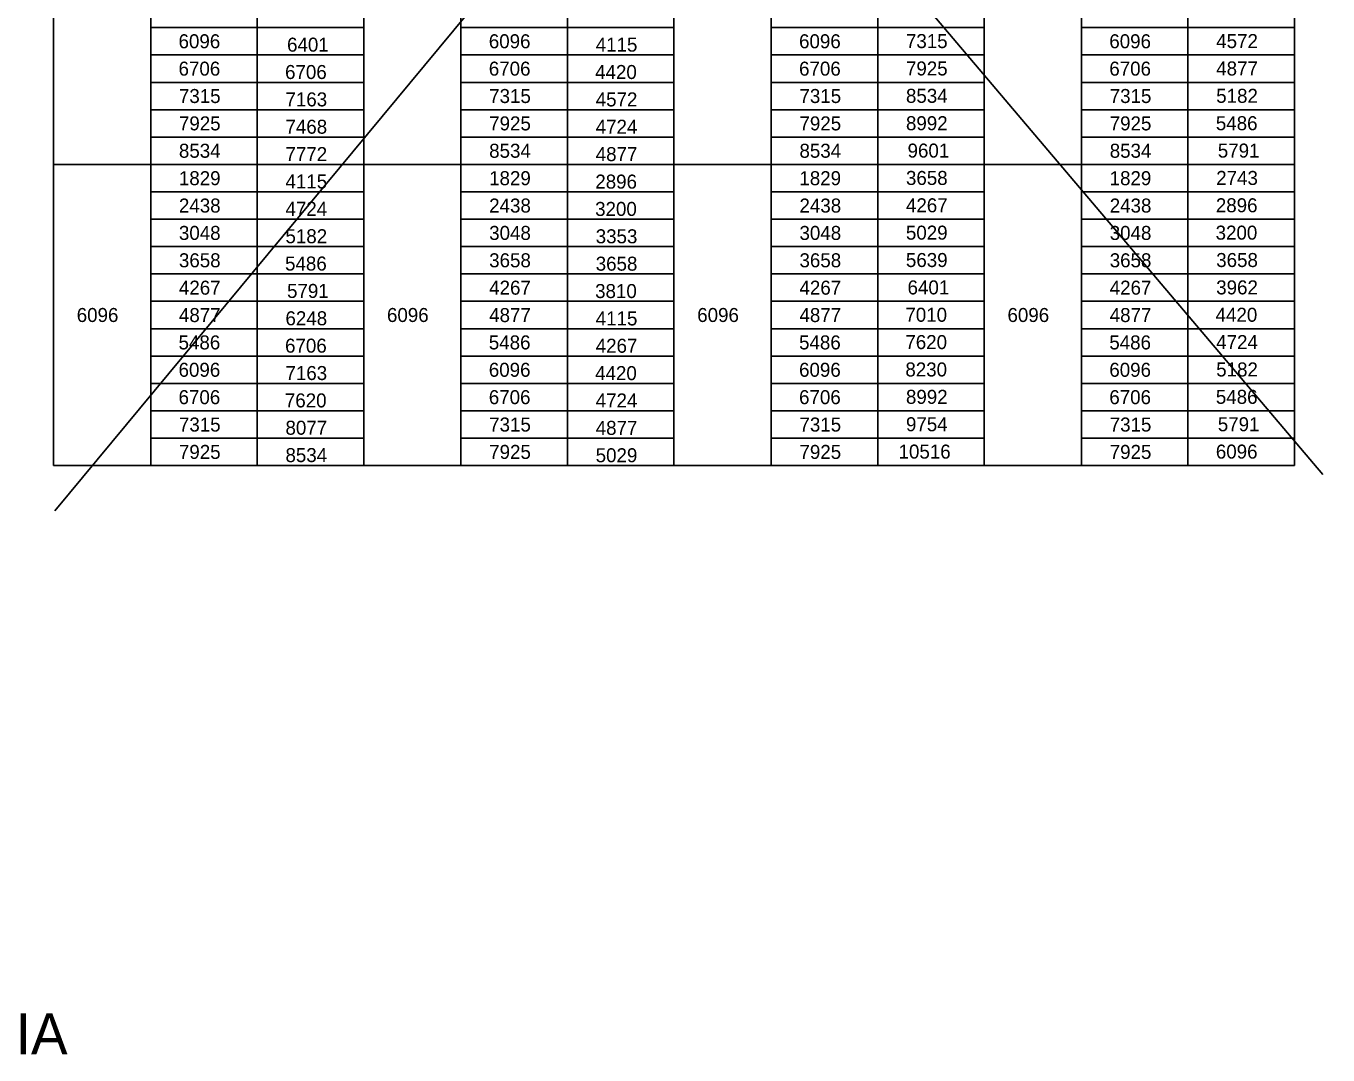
# Model space of a CAD drawing. Extents: x 3475 to 6558, y -3780 to 1166.
# Drawn here: x 4607.5 to 4892.8, y -3463.3 to -3237.8 of the extents above; entities that cross this region are included whole.
import ezdxf

# ---------------------------------------------------------------- set-up
doc = ezdxf.new("R2010")
doc.units = 0
doc.layers.add('1', color=7, linetype='Continuous')
doc.layers.add('2', color=7, linetype='Continuous')

msp = doc.modelspace()

# ---------------------------------------------------------------- linework, layer by layer
at = {"layer": '1'}
for p, q in [((4612.64, -3006.77), (4891.71, -3336.09)), ((4613.49, -3006.18), (4613.49, -3334.12)), ((4885.49, -3006.18), (4885.49, -3334.12)), ((4613.77, -3344.04), (4892.84, -3007.9)), ((4681.49, -3046.18), (4681.49, -3334.12)), ((4749.49, -3046.18), (4749.49, -3334.12)), ((4817.49, -3046.18), (4817.49, -3334.12)), ((4634.82, -3334.12), (4634.82, -3101.36)), ((4658.16, -3101.36), (4658.16, -3334.12)), ((4702.82, -3334.12), (4702.82, -3101.36)), ((4726.16, -3101.36), (4726.16, -3334.12)), ((4770.82, -3334.12), (4770.82, -3101.36)), ((4794.16, -3101.36), (4794.16, -3334.12)), ((4838.83, -3334.12), (4838.83, -3101.36)), ((4862.16, -3101.36), (4862.16, -3334.12)), ((4634.82, -3238.12), (4681.49, -3238.12)), ((4702.82, -3238.12), (4749.49, -3238.12)), ((4770.82, -3238.12), (4817.49, -3238.12)), ((4838.83, -3238.12), (4885.49, -3238.12)), ((4634.82, -3244.12), (4681.49, -3244.12)), ((4702.82, -3244.12), (4749.49, -3244.12)), ((4770.82, -3244.12), (4817.49, -3244.12)), ((4838.83, -3244.12), (4885.49, -3244.12)), ((4634.82, -3250.12), (4681.49, -3250.12)), ((4702.82, -3250.12), (4749.49, -3250.12)), ((4770.82, -3250.12), (4817.49, -3250.12)), ((4838.83, -3250.12), (4885.49, -3250.12)), ((4634.82, -3256.12), (4681.49, -3256.12)), ((4702.82, -3256.12), (4749.49, -3256.12)), ((4770.82, -3256.12), (4817.49, -3256.12)), ((4838.83, -3256.12), (4885.49, -3256.12)), ((4634.82, -3262.12), (4681.49, -3262.12)), ((4702.82, -3262.12), (4749.49, -3262.12)), ((4770.82, -3262.12), (4817.49, -3262.12)), ((4838.83, -3262.12), (4885.49, -3262.12)), ((4613.49, -3268.12), (4885.49, -3268.12)), ((4669.82, -3271.87), (4669.82, -3271.87)), ((4737.82, -3271.87), (4737.82, -3271.87)), ((4805.83, -3271.87), (4805.83, -3271.87)), ((4873.83, -3271.87), (4873.83, -3271.87)), ((4634.82, -3274.12), (4681.49, -3274.12)), ((4634.82, -3274.12), (4681.49, -3274.12)), ((4702.82, -3274.12), (4749.49, -3274.12)), ((4770.82, -3274.12), (4817.49, -3274.12)), ((4838.83, -3274.12), (4885.49, -3274.12)), ((4634.82, -3280.12), (4681.49, -3280.12)), ((4702.82, -3280.12), (4749.49, -3280.12)), ((4770.82, -3280.12), (4817.49, -3280.12)), ((4838.83, -3280.12), (4885.49, -3280.12)), ((4634.82, -3286.12), (4681.49, -3286.12)), ((4702.82, -3286.12), (4749.49, -3286.12)), ((4770.82, -3286.12), (4817.49, -3286.12)), ((4838.83, -3286.12), (4885.49, -3286.12)), ((4634.82, -3292.12), (4681.49, -3292.12)), ((4702.82, -3292.12), (4749.49, -3292.12)), ((4770.82, -3292.12), (4817.49, -3292.12)), ((4838.83, -3292.12), (4885.49, -3292.12)), ((4634.82, -3298.12), (4681.49, -3298.12)), ((4702.82, -3298.12), (4749.49, -3298.12)), ((4770.82, -3298.12), (4817.49, -3298.12)), ((4838.83, -3298.12), (4885.49, -3298.12)), ((4634.82, -3304.12), (4681.49, -3304.12)), ((4702.82, -3304.12), (4749.49, -3304.12)), ((4770.82, -3304.12), (4817.49, -3304.12)), ((4838.83, -3304.12), (4885.49, -3304.12)), ((4634.82, -3310.12), (4681.49, -3310.12)), ((4702.82, -3310.12), (4749.49, -3310.12)), ((4770.82, -3310.12), (4817.49, -3310.12)), ((4838.83, -3310.12), (4885.49, -3310.12)), ((4634.82, -3316.12), (4681.49, -3316.12)), ((4702.82, -3316.12), (4749.49, -3316.12)), ((4770.82, -3316.12), (4817.49, -3316.12)), ((4838.83, -3316.12), (4885.49, -3316.12)), ((4634.82, -3322.12), (4681.49, -3322.12)), ((4702.82, -3322.12), (4749.49, -3322.12)), ((4770.82, -3322.12), (4817.49, -3322.12)), ((4838.83, -3322.12), (4885.49, -3322.12)), ((4634.82, -3328.12), (4681.49, -3328.12)), ((4702.82, -3328.12), (4749.49, -3328.12)), ((4770.82, -3328.12), (4817.49, -3328.12)), ((4838.83, -3328.12), (4885.49, -3328.12)), ((4613.49, -3334.12), (4885.49, -3334.12))]:
    msp.add_line(p, q, dxfattribs=at)

# ---------------------------------------------------------------- texts
for s, p in [('6096', (4640.92, -3242.65)), ('6401', (4664.7, -3243.39)), ('6096', (4708.92, -3242.65)), ('4115', (4732.35, -3243.39)), ('6096', (4776.92, -3242.65)), ('7315', (4800.35, -3242.61)), ('6096', (4844.92, -3242.65)), ('4572', (4868.35, -3242.61)), ('6706', (4640.92, -3248.65)), ('6706', (4664.26, -3249.39)), ('6706', (4708.92, -3248.65)), ('4420', (4732.22, -3249.39)), ('6706', (4776.92, -3248.65)), ('7925', (4800.35, -3248.61)), ('6706', (4844.92, -3248.65)), ('4877', (4868.35, -3248.61)), ('7315', (4641, -3254.65)), ('7163', (4664.35, -3255.39)), ('7315', (4709, -3254.65)), ('4572', (4732.35, -3255.39)), ('7315', (4777.01, -3254.65)), ('8534', (4800.35, -3254.61)), ('7315', (4845.01, -3254.65)), ('5182', (4868.35, -3254.61)), ('7925', (4641, -3260.65)), ('7468', (4664.35, -3261.38)), ('7925', (4709, -3260.65)), ('4724', (4732.35, -3261.38)), ('7925', (4777.01, -3260.65)), ('8992', (4800.35, -3260.61)), ('7925', (4845.01, -3260.65)), ('5486', (4868.27, -3260.61)), ('8534', (4641, -3266.65)), ('7772', (4664.35, -3267.38)), ('8534', (4709, -3266.65)), ('4877', (4732.35, -3267.38)), ('8534', (4777.01, -3266.65)), ('9601', (4800.7, -3266.61)), ('8534', (4845.01, -3266.65)), ('5791', (4868.7, -3266.61)), ('1829', (4640.99, -3272.66)), ('1829', (4708.99, -3272.66)), ('1829', (4776.99, -3272.66)), ('3658', (4800.35, -3272.61)), ('1829', (4844.99, -3272.66)), ('2743', (4868.35, -3272.61)), ('4115', (4664.35, -3273.38)), ('2896', (4732.26, -3273.41)), ('2438', (4641, -3278.66)), ('2438', (4709, -3278.66)), ('2438', (4777.01, -3278.66)), ('4267', (4800.35, -3278.6)), ('2438', (4845.01, -3278.66)), ('2896', (4868.27, -3278.6)), ('4724', (4664.35, -3279.38)), ('3200', (4732.22, -3279.4)), ('3048', (4641, -3284.66)), ('3048', (4709, -3284.66)), ('3048', (4777.01, -3284.66)), ('5029', (4800.34, -3284.6)), ('3048', (4845.01, -3284.66)), ('3200', (4868.22, -3284.6)), ('5182', (4664.35, -3285.38)), ('3353', (4732.35, -3285.4)), ('3658', (4641, -3290.66)), ('5486', (4664.26, -3291.37)), ('3658', (4709, -3290.66)), ('3658', (4732.35, -3291.4)), ('3658', (4777.01, -3290.66)), ('5639', (4800.34, -3290.6)), ('3658', (4845.01, -3290.66)), ('3658', (4868.35, -3290.6)), ('4267', (4641, -3296.66)), ('5791', (4664.7, -3297.37)), ('4267', (4709, -3296.66)), ('3810', (4732.22, -3297.4)), ('4267', (4777.01, -3296.66)), ('6401', (4800.7, -3296.6)), ('4267', (4845.01, -3296.66)), ('3962', (4868.35, -3296.6)), ('6096', (4618.6, -3302.65)), ('4877', (4641, -3302.66)), ('6248', (4664.35, -3303.37)), ('6096', (4686.6, -3302.65)), ('4877', (4709, -3302.66)), ('4115', (4732.35, -3303.4)), ('6096', (4754.6, -3302.65)), ('4877', (4777.01, -3302.66)), ('7010', (4800.22, -3302.6)), ('6096', (4822.6, -3302.65)), ('4877', (4845.01, -3302.66)), ('4420', (4868.22, -3302.6)), ('5486', (4640.92, -3308.66)), ('6706', (4664.26, -3309.37)), ('5486', (4708.92, -3308.66)), ('4267', (4732.35, -3309.39)), ('5486', (4776.92, -3308.66)), ('7620', (4800.22, -3308.59)), ('5486', (4844.92, -3308.66)), ('4724', (4868.35, -3308.59)), ('6096', (4640.92, -3314.66)), ('7163', (4664.35, -3315.37)), ('6096', (4708.92, -3314.66)), ('4420', (4732.22, -3315.39)), ('6096', (4776.92, -3314.66)), ('8230', (4800.22, -3314.59)), ('6096', (4844.92, -3314.66)), ('5182', (4868.35, -3314.59)), ('6706', (4640.92, -3320.66)), ('7620', (4664.22, -3321.37)), ('6706', (4708.92, -3320.66)), ('4724', (4732.35, -3321.39)), ('6706', (4776.92, -3320.66)), ('8992', (4800.35, -3320.59)), ('6706', (4844.92, -3320.66)), ('5486', (4868.27, -3320.59)), ('7315', (4641, -3326.66)), ('8077', (4664.35, -3327.36)), ('7315', (4709, -3326.66)), ('4877', (4732.35, -3327.39)), ('7315', (4777.01, -3326.66)), ('9754', (4800.35, -3326.59)), ('7315', (4845.01, -3326.66)), ('5791', (4868.7, -3326.59)), ('7925', (4641, -3332.66)), ('7925', (4709, -3332.66)), ('7925', (4777.01, -3332.66)), ('10516', (4798.73, -3332.59)), ('7925', (4845.01, -3332.66)), ('6096', (4868.27, -3332.59)), ('8534', (4664.35, -3333.36)), ('5029', (4732.34, -3333.39))]:
    msp.add_text(s, height=3.07, dxfattribs=at).set_placement(p)
at = {"layer": '2'}
msp.add_text('COMMONWEALTH OF PENNSYLVANIA', height=9, dxfattribs=at).set_placement((4394.59, -3463.18))

doc.saveas('drawing.dxf')
